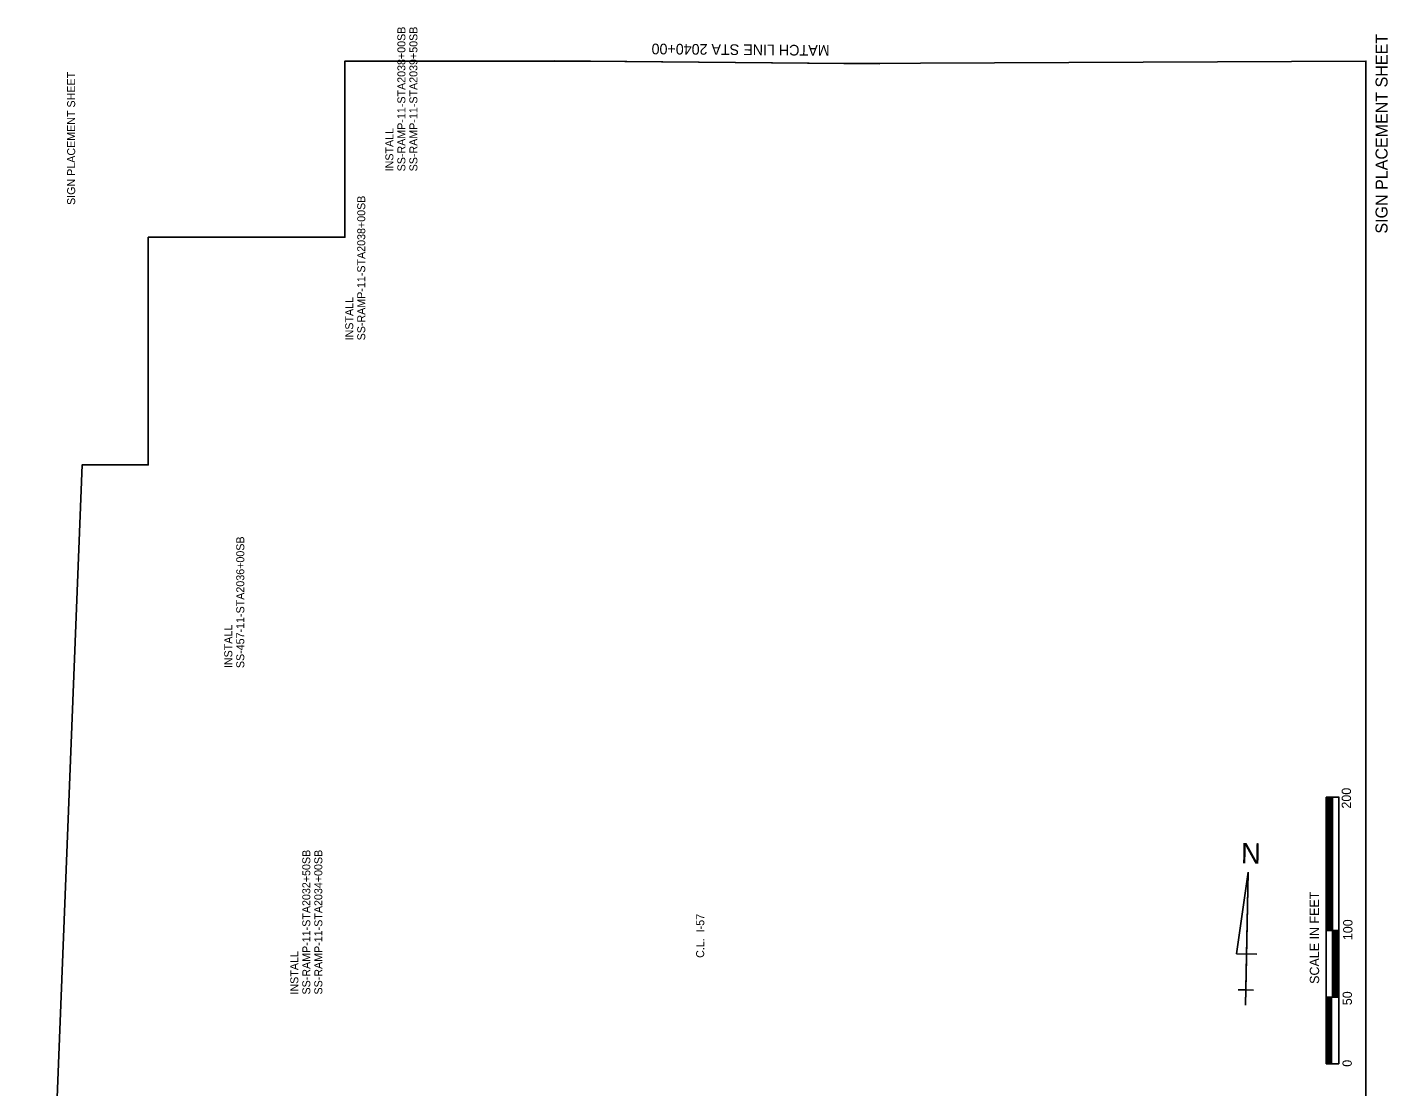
# Model space of a CAD drawing. Extents: x 1713079 to 1714099, y 759509 to 761048.
# Drawn here: x 1713079 to 1714099, y 760253 to 761048 of the extents above; entities that cross this region are included whole.
import ezdxf

# ---------------------------------------------------------------- set-up
doc = ezdxf.new("R2010")
doc.units = 0
for name, color, linetype in [('1', 7, 'Continuous'), ('14', 7, 'Continuous'), ('18', 7, 'Continuous'), ('19', 7, 'Continuous'), ('2', 7, 'Continuous'), ('3', 7, 'Continuous'), ('5', 7, 'Continuous')]:
    doc.layers.add(name, color=color, linetype=linetype)

msp = doc.modelspace()

# ---------------------------------------------------------------- linework, layer by layer
at = {"layer": '18'}
msp.add_line((1713718.2, 761020.7), (1713474.3, 761022.9), dxfattribs=at)
at = {"layer": '19'}
for p, q in [((1714052.9, 760350.5), (1714052.9, 760470.5)), ((1714062.6, 760470.5), (1714053, 760470.5)), ((1714053.7, 760370.5), (1714053.7, 760470.5)), ((1714054.5, 760370.5), (1714054.5, 760470.5)), ((1714055.3, 760370.5), (1714055.3, 760470.5)), ((1714056.1, 760370.5), (1714056.1, 760470.5)), ((1714056.9, 760370.5), (1714056.9, 760470.5)), ((1714057.7, 760370.5), (1714057.7, 760470.5)), ((1714062.5, 760270.5), (1714062.5, 760470.5)), ((1714052.9, 760270.5), (1714052.9, 760430.5)), ((1714057.7, 760370.5), (1714057.7, 760430.5)), ((1714062.6, 760370.5), (1714053, 760370.5)), ((1714057.7, 760320.5), (1714057.7, 760370.5)), ((1714058.6, 760320.5), (1714058.5, 760370.5)), ((1714059.4, 760320.5), (1714059.3, 760370.5)), ((1714060.1, 760320.5), (1714060.1, 760370.5)), ((1714061, 760320.5), (1714060.9, 760370.5)), ((1714061.7, 760320.5), (1714061.7, 760370.5)), ((1714062.5, 760310.5), (1714062.5, 760350.5)), ((1714062.6, 760320.5), (1714053, 760320.5)), ((1714053.7, 760270.5), (1714053.7, 760320.5)), ((1714054.5, 760270.5), (1714054.5, 760320.5)), ((1714055.3, 760270.5), (1714055.3, 760320.5)), ((1714056.2, 760270.5), (1714056.2, 760320.5)), ((1714056.9, 760270.5), (1714056.9, 760320.5)), ((1714052.9, 760270.5), (1714052.9, 760310.5)), ((1714062.5, 760270.5), (1714052.9, 760270.5))]:
    msp.add_line(p, q, dxfattribs=at)
at = {"layer": '2'}
msp.add_lwpolyline([(1714082.8, 759686.7), (1713917, 759649), (1713680.1, 759521), (1713486.2, 759522.7), (1713242.1, 759627.6), (1713079, 759675.8), (1713120.2, 760719.8), (1713169.8, 760719.8), (1713169.8, 760890.6), (1713317.3, 760890.6), (1713317.3, 761022.8), (1713499.3, 761022.6), (1713693.2, 761020.9), (1714082.8, 761022.8)], close=True, dxfattribs=at)
at = {"layer": '3'}
for p, q in [((1713994.5, 760414.3), (1713985.7, 760352.9)), ((1713992.6, 760314.3), (1713994.5, 760414.3)), ((1713994.5, 760414.3), (1713993.1, 760337.4)), ((1713985.7, 760352.9), (1714001, 760352.6)), ((1713992.6, 760314.3), (1713993.1, 760337.4)), ((1713992.8, 760325.9), (1713987.1, 760326)), ((1713987.1, 760326), (1713998.6, 760325.7)), ((1713992.6, 760314.3), (1713992.8, 760325.9))]:
    msp.add_line(p, q, dxfattribs=at)

# ---------------------------------------------------------------- texts
at = {"layer": '1'}
for height, p in [(9, (1714099, 760893.3)), (6, (1713115, 760914.8))]:
    msp.add_text('SIGN PLACEMENT SHEET', height=height, rotation=90, dxfattribs=at).set_placement(p)
at = {"layer": '14'}
for s, p in [('SS-RAMP-11-STA2038+00SB', (1713362.6, 760940)), ('SS-RAMP-11-STA2039+50SB', (1713371.6, 760940)), ('INSTALL', (1713353.6, 760940)), ('SS-RAMP-11-STA2038+00SB', (1713332.5, 760813.2)), ('INSTALL', (1713323.5, 760813.2)), ('SS-457-11-STA2036+00SB', (1713241.8, 760567.3)), ('INSTALL', (1713232.8, 760567.3)), ('SS-RAMP-11-STA2032+50SB', (1713291.3, 760322.4)), ('SS-RAMP-11-STA2034+00SB', (1713300.3, 760322.4)), ('INSTALL', (1713282.3, 760322.4))]:
    msp.add_text(s, height=6, rotation=90, dxfattribs=at).set_placement(p)
at = {"layer": '18'}
msp.add_text('MATCH LINE STA 2040+00', height=8, rotation=179.5, dxfattribs=at).set_placement((1713680.7, 761034.7))
at = {"layer": '19'}
for s, height, p in [('200', 7, (1714071.6, 760461.9)), ('SCALE IN FEET', 7.001, (1714047.7, 760330.4)), ('100', 7, (1714072.7, 760363.2)), ('50', 7, (1714072.3, 760314.4)), ('0', 7, (1714072.2, 760268.2))]:
    msp.add_text(s, height=height, rotation=90.0003, dxfattribs=at).set_placement(p)
at = {"layer": '3'}
msp.add_text('N', height=15.4, rotation=358.9083, dxfattribs=at).set_placement((1713989, 760420.8))
at = {"layer": '5'}
msp.add_text('C.L.  I-57', height=6, rotation=89.8523, dxfattribs=at).set_placement((1713586.6, 760349.9))

doc.saveas('drawing.dxf')
